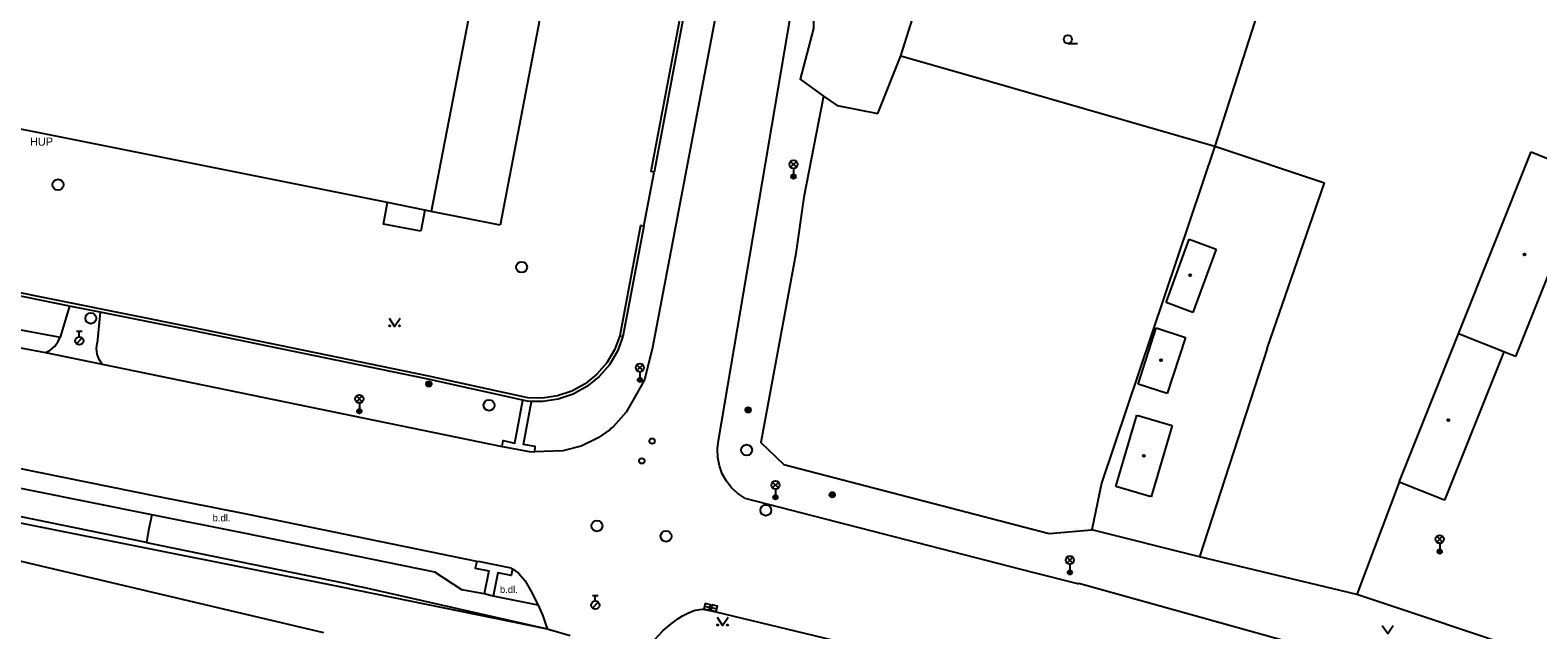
# Model space of a CAD drawing. Extents: x -598233 to -596890, y -1157848 to -1156431.
# Drawn here: x -597502.6 to -597364.6, y -1157653.8 to -1157598.9 of the extents above; entities that cross this region are included whole.
import ezdxf

# ---------------------------------------------------------------- set-up
doc = ezdxf.new("R2010")
doc.units = 0
for name, color, linetype in [('Level 10', 7, 'Continuous'), ('Level 11', 7, 'Continuous'), ('Level 25', 7, 'Continuous'), ('Level 27', 7, 'Continuous'), ('Level 28', 7, 'Continuous'), ('Level 33', 7, 'Continuous'), ('Level 36', 7, 'Continuous'), ('Level 39', 7, 'Continuous'), ('Level 40', 7, 'Continuous'), ('Level 41', 7, 'Continuous'), ('Level 5', 7, 'Continuous'), ('Level 7', 7, 'Continuous'), ('Level 8', 7, 'Continuous')]:
    doc.layers.add(name, color=color, linetype=linetype)

msp = doc.modelspace()

# ---------------------------------------------------------------- linework, layer by layer
at = {"layer": 'Level 10'}
for points in [[(-597437.06, -1157582.87), (-597445.64, -1157627.94), (-597446.38, -1157630.9), (-597447.19, -1157632.38)], [(-597439.59, -1157636.45), (-597430.69, -1157583.94)], [(-597505.35, -1157627.62), (-597503.4819, -1157627.9801), (-597501.2, -1157628.42)], [(-597501.2, -1157628.42), (-597496, -1157629.48)], [(-597496, -1157629.48), (-597459.4099, -1157637.01)], [(-597447.19, -1157632.38), (-597448.06, -1157633.88), (-597449.2199, -1157635.17), (-597449.44, -1157635.37), (-597449.52, -1157635.44), (-597450.61, -1157636.2199), (-597452.17, -1157636.9699), (-597453.85, -1157637.4), (-597455.59, -1157637.48), (-597456.4, -1157637.5)], [(-597459.4099, -1157637.01), (-597458.89, -1157637.11), (-597456.9099, -1157637.46), (-597456.4, -1157637.5)], [(-597437.17, -1157641.75), (-597437.81, -1157641.32), (-597438.39, -1157640.8), (-597438.87, -1157640.18), (-597439.25, -1157639.5), (-597439.51, -1157638.77), (-597439.6599, -1157638.01), (-597439.69, -1157637.23), (-597439.59, -1157636.45)], [(-597491.12, -1157641.55), (-597507.85, -1157638.1599)], [(-597461.71, -1157647.53), (-597482.6599, -1157643.24), (-597491.12, -1157641.55)], [(-597437.17, -1157641.75), (-597410.86, -1157648.5)], [(-597458.57, -1157648.14), (-597461.4099, -1157647.57), (-597461.71, -1157647.53)], [(-597458.57, -1157648.14), (-597458.44, -1157648.21)], [(-597458.44, -1157648.21), (-597458.03, -1157648.51), (-597457.87, -1157648.62), (-597457.29, -1157649.3), (-597456.76, -1157650.23), (-597456.09, -1157651.53)], [(-597410.86, -1157648.5), (-597406.72, -1157649.54), (-597406.62, -1157649.56)], [(-597382.9699, -1157656.14), (-597406.62, -1157649.56)], [(-597456.09, -1157651.53), (-597455.67, -1157652.5), (-597455.28, -1157653.68)], [(-597446.09, -1157655.49), (-597445.49, -1157654.73), (-597444.67, -1157653.85), (-597443.94, -1157653.23), (-597443.32, -1157652.77), (-597442.9, -1157652.5), (-597442.4099, -1157652.25), (-597441.81, -1157652.02), (-597441.69, -1157652), (-597441.08, -1157651.88), (-597440.69, -1157651.94), (-597439.85, -1157652.14)], [(-597439.85, -1157652.14), (-597426.79, -1157655.29), (-597412.21, -1157658.94), (-597411.82, -1157659.06)]]:
    msp.add_lwpolyline(points, dxfattribs=at)
at = {"layer": 'Level 11'}
for points in [[(-597430.88, -1157596.24), (-597430.91, -1157598.78), (-597432.11, -1157603.4), (-597429.98, -1157604.96)], [(-597425, -1157606.55), (-597422.91, -1157601.26)], [(-597422.9099, -1157601.26), (-597414.49, -1157603.68)], [(-597414.49, -1157603.68), (-597394.17, -1157609.53)], [(-597429.98, -1157604.96), (-597431.78, -1157614.19), (-597432.5, -1157619.36), (-597435.71, -1157636.63), (-597433.6, -1157638.66)], [(-597429.98, -1157604.96), (-597428.73, -1157605.81), (-597425, -1157606.55)], [(-597491.96, -1157645.79), (-597508.68, -1157642.39), (-597510.96, -1157641.92), (-597511.41, -1157641.83), (-597535.12, -1157637), (-597535.65, -1157636.89), (-597547.1, -1157634.56), (-597547.18, -1157634.54), (-597553.34, -1157633.29), (-597561.28, -1157631.65), (-597561.64, -1157631.58), (-597578.94, -1157628), (-597585.37, -1157626.71), (-597586, -1157626.59), (-597601.76, -1157623.43), (-597601.71, -1157623.44), (-597608.51, -1157622.07), (-597608.71, -1157622.03), (-597631.86, -1157617.38), (-597642.86, -1157615.26), (-597643.46, -1157615.15), (-597647.47, -1157614.38), (-597647.55, -1157614.36), (-597675.48, -1157609)], [(-597394.17, -1157609.53), (-597384.12, -1157612.88)], [(-597389.37, -1157628.04), (-597384.12, -1157612.88)], [(-597470.26, -1157616.6599), (-597469.89, -1157614.7)], [(-597466.83, -1157617.31), (-597470.26, -1157616.6599)], [(-597466.46, -1157615.39), (-597466.83, -1157617.31)], [(-597527.84, -1157621.82), (-597517.4342, -1157623.7531), (-597499.85, -1157627.02)], [(-597602.44, -1157624.18), (-597475.74, -1157654.04)], [(-597499.01, -1157624.17), (-597499.85, -1157627.02)], [(-597496.2, -1157624.73), (-597496.48, -1157627.55)], [(-597501.2, -1157628.42), (-597500.76, -1157628.19), (-597500.38, -1157627.87), (-597500.07, -1157627.4699), (-597499.85, -1157627.02)], [(-597496, -1157629.48), (-597496.29, -1157629.05), (-597496.4699, -1157628.57), (-597496.54, -1157628.06), (-597496.48, -1157627.55)], [(-597459.4099, -1157637.01), (-597459.3, -1157636.4699), (-597458.23, -1157636.7), (-597457.51, -1157632.78)], [(-597456.4, -1157637.5), (-597456.36, -1157637.01), (-597457.45, -1157636.83), (-597456.71, -1157632.88)], [(-597461.03, -1157650.48), (-597463.1, -1157650.13), (-597465.56, -1157648.5), (-597483.03, -1157644.94), (-597491.4609, -1157643.2511), (-597508.19, -1157639.9), (-597507.85, -1157638.1599)], [(-597433.6, -1157638.66), (-597409.34, -1157644.97), (-597405.41, -1157644.63)], [(-597491.46, -1157643.25), (-597491.77, -1157644.66), (-597491.96, -1157645.79), (-597473.8, -1157649.52), (-597472.62, -1157649.78), (-597472.12, -1157649.89), (-597455.28, -1157653.68)], [(-597461.71, -1157647.53), (-597461.88, -1157648.13), (-597460.62, -1157648.4), (-597461.03, -1157650.48)], [(-597458.44, -1157648.21), (-597458.57, -1157648.81), (-597459.79, -1157648.57), (-597460.2199, -1157650.7)], [(-597460.2199, -1157650.7), (-597461.03, -1157650.48)], [(-597456.09, -1157651.53), (-597460.2199, -1157650.7)]]:
    msp.add_lwpolyline(points, dxfattribs=at)
at = {"layer": 'Level 25'}
for centre, radius in [((-597466.1, -1157631.28), 0.25), ((-597466.1, -1157631.28), 0.2), ((-597466.1, -1157631.28), 0.15), ((-597466.1, -1157631.28), 0.1), ((-597466.1, -1157631.28), 0.05), ((-597436.88, -1157633.66), 0.25), ((-597436.88, -1157633.66), 0.2), ((-597436.88, -1157633.66), 0.15), ((-597436.88, -1157633.66), 0.1), ((-597436.88, -1157633.66), 0.05), ((-597429.18, -1157641.43), 0.25), ((-597429.18, -1157641.43), 0.2), ((-597429.18, -1157641.43), 0.15), ((-597429.18, -1157641.43), 0.1), ((-597429.18, -1157641.43), 0.05)]:
    msp.add_circle(centre, radius, dxfattribs=at)
at = {"layer": 'Level 27'}
for p, q in [((-597440.8624, -1157651.6186), (-597440.3776, -1157651.7414)), ((-597440.2324, -1157651.7486), (-597439.7476, -1157651.8714))]:
    msp.add_line(p, q, dxfattribs=at)
for points in [[(-597440.9237, -1157651.861), (-597440.439, -1157651.9837), (-597440.3163, -1157651.499), (-597440.801, -1157651.3763)], [(-597440.2937, -1157651.991), (-597439.809, -1157652.1137), (-597439.6863, -1157651.629), (-597440.171, -1157651.5063)]]:
    msp.add_lwpolyline(points, close=True, dxfattribs=at)
for centre in [(-597500.05, -1157613.06), (-597457.62, -1157620.6), (-597497.05, -1157625.28), (-597460.59, -1157633.24), (-597437.02, -1157637.34), (-597435.26, -1157642.84), (-597450.7199, -1157644.28), (-597444.39, -1157645.2199)]:
    msp.add_circle(centre, 0.5, dxfattribs=at)
at = {"layer": 'Level 28'}
for p, q in [((-597498.358, -1157627.612), (-597497.828, -1157627.082)), ((-597498.35, -1157626.465), (-597497.85, -1157626.465)), ((-597498.1, -1157626.965), (-597498.1, -1157626.465)), ((-597451.12, -1157650.645), (-597450.62, -1157650.645)), ((-597450.87, -1157651.145), (-597450.87, -1157650.645)), ((-597451.128, -1157651.792), (-597450.598, -1157651.262))]:
    msp.add_line(p, q, dxfattribs=at)
for centre, radius in [((-597498.1, -1157627.34), 0.375), ((-597445.67, -1157636.52), 0.25), ((-597446.61, -1157638.33), 0.25), ((-597450.87, -1157651.52), 0.375)]:
    msp.add_circle(centre, radius, dxfattribs=at)
at = {"layer": 'Level 33'}
for p, q in [((-597432.995, -1157611.45), (-597432.465, -1157610.92)), ((-597432.995, -1157610.92), (-597432.465, -1157611.45)), ((-597432.73, -1157611.56), (-597432.73, -1157612.31)), ((-597447.055, -1157630.06), (-597446.525, -1157629.53)), ((-597447.055, -1157629.53), (-597446.525, -1157630.06)), ((-597446.79, -1157630.17), (-597446.79, -1157630.92)), ((-597472.7349, -1157632.92), (-597472.2049, -1157632.39)), ((-597472.7349, -1157632.39), (-597472.2049, -1157632.92)), ((-597472.4699, -1157633.03), (-597472.4699, -1157633.78)), ((-597434.645, -1157640.7999), (-597434.115, -1157640.2699)), ((-597434.645, -1157640.2699), (-597434.115, -1157640.7999)), ((-597434.38, -1157640.9099), (-597434.38, -1157641.6599)), ((-597373.845, -1157645.76), (-597373.315, -1157645.23)), ((-597373.845, -1157645.23), (-597373.315, -1157645.76)), ((-597373.58, -1157645.87), (-597373.58, -1157646.62)), ((-597407.695, -1157647.67), (-597407.165, -1157647.14)), ((-597407.695, -1157647.14), (-597407.165, -1157647.67)), ((-597407.43, -1157647.78), (-597407.43, -1157648.53))]:
    msp.add_line(p, q, dxfattribs=at)
for centre, radius in [((-597432.73, -1157611.185), 0.375), ((-597432.73, -1157612.31), 0.2), ((-597432.73, -1157612.31), 0.1445), ((-597432.73, -1157612.31), 0.0876), ((-597446.79, -1157629.795), 0.375), ((-597446.79, -1157630.92), 0.2), ((-597446.79, -1157630.92), 0.1445), ((-597446.79, -1157630.92), 0.0876), ((-597472.4699, -1157632.655), 0.375), ((-597472.4699, -1157633.78), 0.2), ((-597472.4699, -1157633.78), 0.1445), ((-597472.4699, -1157633.78), 0.0876), ((-597434.38, -1157640.5349), 0.375), ((-597434.38, -1157641.6599), 0.2), ((-597434.38, -1157641.6599), 0.1445), ((-597434.38, -1157641.6599), 0.0876), ((-597373.58, -1157645.495), 0.375), ((-597407.43, -1157647.405), 0.375), ((-597373.58, -1157646.62), 0.2), ((-597373.58, -1157646.62), 0.1445), ((-597373.58, -1157646.62), 0.0876), ((-597407.43, -1157648.53), 0.2), ((-597407.43, -1157648.53), 0.1445), ((-597407.43, -1157648.53), 0.0876)]:
    msp.add_circle(centre, radius, dxfattribs=at)
at = {"layer": 'Level 36'}
msp.add_line((-597407.62, -1157600.135), (-597406.745, -1157600.135), dxfattribs=at)
for points in [[(-597469.74, -1157625.27), (-597469.24, -1157626.02), (-597468.74, -1157625.27)], [(-597439.7199, -1157652.64), (-597439.2199, -1157653.39), (-597438.7199, -1157652.64)], [(-597378.84, -1157653.38), (-597378.34, -1157654.13), (-597377.84, -1157653.38)]]:
    msp.add_lwpolyline(points, dxfattribs=at)
for centre, radius in [((-597407.6201, -1157599.7599), 0.375), ((-597469.6902, -1157625.9698), 0.05), ((-597468.7908, -1157625.9698), 0.05), ((-597439.6701, -1157653.3398), 0.05), ((-597438.7707, -1157653.3398), 0.05)]:
    msp.add_circle(centre, radius, dxfattribs=at)
at = {"layer": 'Level 39'}
for centre, radius in [((-597365.82, -1157619.44), 0.09), ((-597365.82, -1157619.44), 0.0398), ((-597396.4099, -1157621.34), 0.09), ((-597396.4099, -1157621.34), 0.0398), ((-597399.09, -1157629.12), 0.09), ((-597399.09, -1157629.12), 0.0398), ((-597372.79, -1157634.6), 0.09), ((-597372.79, -1157634.6), 0.0398), ((-597400.6599, -1157637.86), 0.09), ((-597400.6599, -1157637.86), 0.0398)]:
    msp.add_circle(centre, radius, dxfattribs=at)
at = {"layer": 'Level 5'}
for points in [[(-597450.45, -1157569.2), (-597459.58, -1157616.77)], [(-597457.29, -1157571.02), (-597465.9099, -1157615.5)], [(-597469.89, -1157614.7), (-597502.53, -1157608.16), (-597503.03, -1157608.06), (-597537.05, -1157601.25)], [(-597371.87, -1157626.69), (-597365.21, -1157610.04)], [(-597365.21, -1157610.04), (-597359.98, -1157612.14)], [(-597359.98, -1157612.14), (-597366.65, -1157628.78)], [(-597466.46, -1157615.39), (-597469.89, -1157614.7)], [(-597465.9099, -1157615.5), (-597466.46, -1157615.39)], [(-597459.58, -1157616.77), (-597465.9099, -1157615.5)], [(-597398.62, -1157623.84), (-597396.5, -1157618.04)], [(-597396.5, -1157618.04), (-597394.05, -1157618.94)], [(-597394.05, -1157618.94), (-597396.17, -1157624.74)], [(-597396.17, -1157624.74), (-597398.62, -1157623.84)], [(-597401.19, -1157631.3), (-597399.52, -1157626.1599)], [(-597399.52, -1157626.1599), (-597396.84, -1157627.03)], [(-597396.84, -1157627.03), (-597398.51, -1157632.17)], [(-597377.3, -1157640.26), (-597371.87, -1157626.69)], [(-597367.7, -1157628.36), (-597371.87, -1157626.69)], [(-597367.7, -1157628.36), (-597373.13, -1157641.93)], [(-597366.65, -1157628.78), (-597367.7, -1157628.36)], [(-597398.51, -1157632.17), (-597401.19, -1157631.3)], [(-597403.23, -1157640.6599), (-597401.31, -1157634.14)], [(-597401.31, -1157634.14), (-597398.06, -1157635.1)], [(-597398.06, -1157635.1), (-597399.98, -1157641.62)], [(-597399.98, -1157641.62), (-597403.23, -1157640.6599)], [(-597373.13, -1157641.93), (-597377.3, -1157640.26)]]:
    msp.add_lwpolyline(points, dxfattribs=at)
at = {"layer": 'Level 7'}
for points in [[(-597380.08, -1157565.54), (-597385.66, -1157582.97), (-597394.17, -1157609.53)], [(-597439.21, -1157576.98), (-597445.79, -1157611.85)], [(-597438.9099, -1157577.04), (-597445.49, -1157611.9)], [(-597422.9099, -1157601.26), (-597422.02, -1157598.45), (-597420.76, -1157594.44)], [(-597394.17, -1157609.53), (-597404.55, -1157640.38), (-597405.4099, -1157644.63)], [(-597445.49, -1157611.9), (-597445.79, -1157611.85)], [(-597446.7199, -1157616.8), (-597448.62, -1157626.87)], [(-597446.43, -1157616.85), (-597448.34, -1157626.95)], [(-597446.43, -1157616.85), (-597446.7199, -1157616.8)], [(-597499.01, -1157624.17), (-597505.58, -1157622.83), (-597506.01, -1157622.73)], [(-597487.73, -1157626.11), (-597505.53, -1157622.54), (-597505.95, -1157622.46)], [(-597496.2, -1157624.73), (-597499.01, -1157624.17)], [(-597487.79, -1157626.4099), (-597496.2, -1157624.73)], [(-597466.27, -1157630.54), (-597487.73, -1157626.11)], [(-597466.33, -1157630.83), (-597487.79, -1157626.4099)], [(-597448.62, -1157626.87), (-597449.12, -1157628.1599), (-597449.82, -1157629.35), (-597450.73, -1157630.4), (-597451.81, -1157631.27), (-597453.02, -1157631.94), (-597454.33, -1157632.39), (-597455.7, -1157632.6), (-597457.05, -1157632.57)], [(-597448.34, -1157626.95), (-597448.85, -1157628.3), (-597449.58, -1157629.53), (-597450.52, -1157630.62), (-597451.64, -1157631.52), (-597452.9, -1157632.2199), (-597454.26, -1157632.68), (-597455.68, -1157632.9), (-597456.71, -1157632.88)], [(-597448.62, -1157626.87), (-597448.34, -1157626.95)], [(-597389.37, -1157628.04), (-597395.57, -1157647.1)], [(-597457.51, -1157632.78), (-597466.33, -1157630.83)], [(-597457.05, -1157632.57), (-597466.27, -1157630.54)], [(-597457.12, -1157632.87), (-597457.51, -1157632.78)], [(-597456.71, -1157632.88), (-597457.12, -1157632.87)], [(-597554.19, -1157633.89), (-597491.4256, -1157646.3942), (-597474.28, -1157649.81)], [(-597377.3, -1157640.26), (-597381.15, -1157650.54)], [(-597395.57, -1157647.1), (-597405.4099, -1157644.63)], [(-597381.15, -1157650.54), (-597395.57, -1157647.1)], [(-597474.28, -1157649.81), (-597455.28, -1157653.68)], [(-597363.3, -1157656.54), (-597375.03, -1157652.6), (-597381.15, -1157650.54)], [(-597455.28, -1157653.68), (-597453.1599, -1157654.3)]]:
    msp.add_lwpolyline(points, dxfattribs=at)
at = {"layer": 'Level 8'}
msp.add_lwpolyline([(-597446.43, -1157616.85), (-597445.49, -1157611.9)], dxfattribs=at)

# ---------------------------------------------------------------- texts
at = {"layer": 'Level 40'}
for p in [(-597485.9, -1157643.86), (-597459.6, -1157650.42)]:
    msp.add_text('b.dl.', height=0.65, dxfattribs=at).set_placement(p)
at = {"layer": 'Level 41'}
msp.add_text('HUP', height=0.75, dxfattribs=at).set_placement((-597502.62, -1157609.49))

doc.saveas('drawing.dxf')
